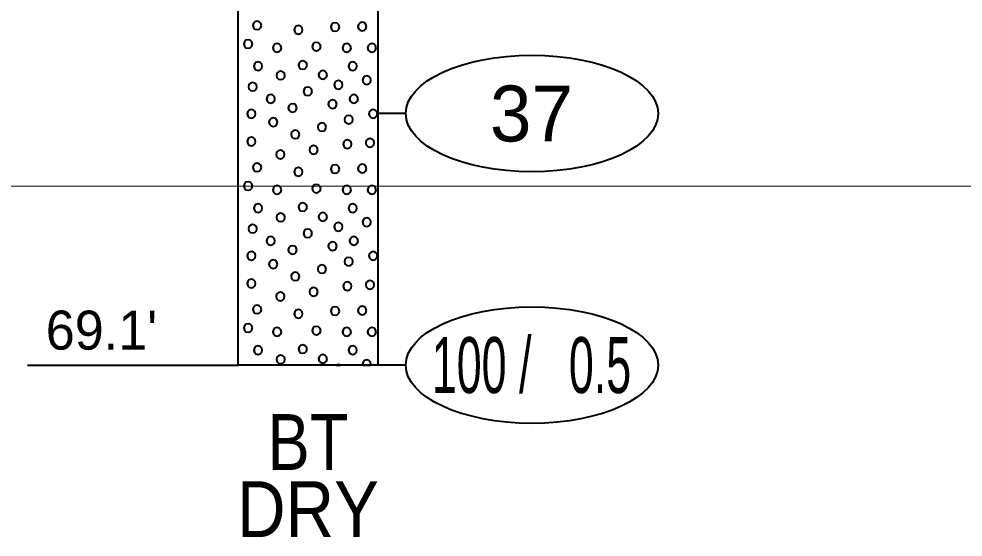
# Model space of a CAD drawing. Extents: x -582 to 653, y -817 to -3.
# Drawn here: x -45.24 to -28.34, y -765.83 to -756.56 of the extents above; entities that cross this region are included whole.
import ezdxf
from ezdxf.enums import TextEntityAlignment as Align

# ---------------------------------------------------------------- set-up
doc = ezdxf.new("R2010")
doc.units = 0
doc.header["$LTSCALE"] = 0.4
doc.layers.add('27', color=7, linetype='Continuous', lineweight=40)
doc.layers.add('7', color=7, linetype='Continuous', lineweight=13)

msp = doc.modelspace()

# ---------------------------------------------------------------- linework, layer by layer
at = {"layer": '27'}
for p, q in [((-38.3189, -758.2526), (-38.8189, -758.2526)), ((-45.0863, -762.7525), (-41.3189, -762.7525)), ((-38.3189, -762.7526), (-38.8189, -762.7526))]:
    msp.add_line(p, q, dxfattribs=at)
for points in [[(-41.3189, -754.6526), (-38.8189, -754.6526), (-38.8189, -762.7525), (-41.3189, -762.7525)], [(-40.9031, -756.6759), (-40.9133, -756.6378), (-40.9412, -756.61), (-40.9793, -756.5997), (-41.0174, -756.61), (-41.0453, -756.6378), (-41.0555, -756.6759), (-41.0453, -756.714), (-41.0174, -756.7419), (-40.9793, -756.7521), (-40.9412, -756.7419), (-40.9133, -756.714)], [(-40.1645, -756.756), (-40.1747, -756.7179), (-40.2026, -756.69), (-40.2407, -756.6798), (-40.2788, -756.69), (-40.3067, -756.7179), (-40.3169, -756.756), (-40.3067, -756.7941), (-40.2788, -756.822), (-40.2407, -756.8322), (-40.2026, -756.822), (-40.1747, -756.7941)], [(-39.5072, -756.7052), (-39.5174, -756.6671), (-39.5453, -756.6392), (-39.5834, -756.629), (-39.6215, -756.6392), (-39.6494, -756.6671), (-39.6596, -756.7052), (-39.6494, -756.7433), (-39.6215, -756.7712), (-39.5834, -756.7814), (-39.5453, -756.7712), (-39.5174, -756.7433)], [(-39.0216, -756.6976), (-39.0318, -756.6595), (-39.0597, -756.6316), (-39.0978, -756.6214), (-39.1359, -756.6316), (-39.1638, -756.6595), (-39.174, -756.6976), (-39.1638, -756.7357), (-39.1359, -756.7636), (-39.0978, -756.7738), (-39.0597, -756.7636), (-39.0318, -756.7357)], [(-41.0645, -757.009), (-41.0747, -756.9709), (-41.1026, -756.943), (-41.1407, -756.9328), (-41.1788, -756.943), (-41.2067, -756.9709), (-41.2169, -757.009), (-41.2067, -757.0471), (-41.1788, -757.075), (-41.1407, -757.0852), (-41.1026, -757.075), (-41.0747, -757.0471)], [(-40.5458, -757.0789), (-40.5561, -757.0408), (-40.5839, -757.0129), (-40.622, -757.0027), (-40.6601, -757.0129), (-40.688, -757.0408), (-40.6982, -757.0789), (-40.688, -757.117), (-40.6601, -757.1449), (-40.622, -757.1551), (-40.5839, -757.1449), (-40.5561, -757.117)], [(-39.8416, -757.0561), (-39.8518, -757.018), (-39.8797, -756.9901), (-39.9178, -756.9799), (-39.9559, -756.9901), (-39.9838, -757.018), (-39.994, -757.0561), (-39.9838, -757.0942), (-39.9559, -757.122), (-39.9178, -757.1323), (-39.8797, -757.122), (-39.8518, -757.0942)], [(-39.2987, -757.0789), (-39.3089, -757.0408), (-39.3368, -757.0129), (-39.3749, -757.0027), (-39.413, -757.0129), (-39.4409, -757.0408), (-39.4511, -757.0789), (-39.4409, -757.117), (-39.413, -757.1449), (-39.3749, -757.1551), (-39.3368, -757.1449), (-39.3089, -757.117)], [(-38.8487, -757.0789), (-38.8589, -757.0408), (-38.8868, -757.0129), (-38.9249, -757.0027), (-38.963, -757.0129), (-38.9909, -757.0408), (-39.0011, -757.0789), (-38.9909, -757.117), (-38.963, -757.1449), (-38.9249, -757.1551), (-38.8868, -757.1449), (-38.8589, -757.117)], [(-40.887, -757.4052), (-40.8972, -757.3671), (-40.9251, -757.3392), (-40.9632, -757.329), (-41.0013, -757.3392), (-41.0292, -757.3671), (-41.0394, -757.4052), (-41.0292, -757.4433), (-41.0013, -757.4712), (-40.9632, -757.4814), (-40.9251, -757.4712), (-40.8972, -757.4433)], [(-40.086, -757.3856), (-40.0962, -757.3475), (-40.1241, -757.3196), (-40.1622, -757.3094), (-40.2003, -757.3196), (-40.2282, -757.3475), (-40.2384, -757.3856), (-40.2282, -757.4237), (-40.2003, -757.4516), (-40.1622, -757.4618), (-40.1241, -757.4516), (-40.0962, -757.4237)], [(-39.1924, -757.4053), (-39.2026, -757.3672), (-39.2305, -757.3393), (-39.2686, -757.3291), (-39.3067, -757.3393), (-39.3346, -757.3672), (-39.3448, -757.4053), (-39.3346, -757.4434), (-39.3067, -757.4713), (-39.2686, -757.4815), (-39.2305, -757.4713), (-39.2026, -757.4434)], [(-40.482, -757.5705), (-40.4923, -757.5324), (-40.5201, -757.5045), (-40.5582, -757.4943), (-40.5963, -757.5045), (-40.6242, -757.5324), (-40.6344, -757.5705), (-40.6242, -757.6086), (-40.5963, -757.6365), (-40.5582, -757.6467), (-40.5201, -757.6365), (-40.4923, -757.6086)], [(-39.727, -757.5615), (-39.7372, -757.5234), (-39.7651, -757.4955), (-39.8032, -757.4853), (-39.8413, -757.4955), (-39.8692, -757.5234), (-39.8794, -757.5615), (-39.8692, -757.5996), (-39.8413, -757.6275), (-39.8032, -757.6377), (-39.7651, -757.6275), (-39.7372, -757.5996)], [(-38.9415, -757.6574), (-38.9517, -757.6193), (-38.9796, -757.5914), (-39.0177, -757.5812), (-39.0558, -757.5914), (-39.0837, -757.6193), (-39.0939, -757.6574), (-39.0837, -757.6955), (-39.0558, -757.7234), (-39.0177, -757.7336), (-38.9796, -757.7234), (-38.9517, -757.6955)], [(-40.9832, -757.7731), (-40.9934, -757.735), (-41.0213, -757.7071), (-41.0594, -757.6969), (-41.0975, -757.7071), (-41.1254, -757.735), (-41.1356, -757.7731), (-41.1254, -757.8112), (-41.0975, -757.839), (-41.0594, -757.8493), (-41.0213, -757.839), (-40.9934, -757.8112)], [(-39.9971, -757.8563), (-40.0073, -757.8182), (-40.0352, -757.7903), (-40.0733, -757.7801), (-40.1114, -757.7903), (-40.1393, -757.8182), (-40.1495, -757.8563), (-40.1393, -757.8944), (-40.1114, -757.9222), (-40.0733, -757.9325), (-40.0352, -757.9222), (-40.0073, -757.8944)], [(-39.4487, -757.7387), (-39.459, -757.7006), (-39.4868, -757.6727), (-39.5249, -757.6625), (-39.563, -757.6727), (-39.5909, -757.7006), (-39.6011, -757.7387), (-39.5909, -757.7768), (-39.563, -757.8047), (-39.5249, -757.8149), (-39.4868, -757.8047), (-39.459, -757.7768)], [(-40.6603, -757.9917), (-40.6705, -757.9536), (-40.6984, -757.9257), (-40.7365, -757.9155), (-40.7746, -757.9257), (-40.8025, -757.9536), (-40.8127, -757.9917), (-40.8025, -758.0298), (-40.7746, -758.0577), (-40.7365, -758.0679), (-40.6984, -758.0577), (-40.6705, -758.0298)], [(-39.1716, -757.9917), (-39.1818, -757.9536), (-39.2097, -757.9257), (-39.2478, -757.9155), (-39.2859, -757.9257), (-39.3138, -757.9536), (-39.324, -757.9917), (-39.3138, -758.0298), (-39.2859, -758.0577), (-39.2478, -758.0679), (-39.2097, -758.0577), (-39.1818, -758.0298)], [(-40.2687, -758.1532), (-40.2789, -758.1151), (-40.3068, -758.0872), (-40.3449, -758.077), (-40.383, -758.0872), (-40.4109, -758.1151), (-40.4211, -758.1532), (-40.4109, -758.1913), (-40.383, -758.2192), (-40.3449, -758.2294), (-40.3068, -758.2192), (-40.2789, -758.1913)], [(-39.553, -758.0845), (-39.5632, -758.0464), (-39.5911, -758.0185), (-39.6292, -758.0083), (-39.6673, -758.0185), (-39.6952, -758.0464), (-39.7054, -758.0845), (-39.6952, -758.1226), (-39.6673, -758.1505), (-39.6292, -758.1607), (-39.5911, -758.1505), (-39.5632, -758.1226)], [(-41.006, -758.2574), (-41.0163, -758.2193), (-41.0441, -758.1914), (-41.0822, -758.1812), (-41.1203, -758.1914), (-41.1482, -758.2193), (-41.1584, -758.2574), (-41.1482, -758.2955), (-41.1203, -758.3234), (-41.0822, -758.3336), (-41.0441, -758.3234), (-41.0163, -758.2955)], [(-39.2644, -758.3617), (-39.2746, -758.3236), (-39.3025, -758.2957), (-39.3406, -758.2855), (-39.3787, -758.2957), (-39.4066, -758.3236), (-39.4168, -758.3617), (-39.4066, -758.3998), (-39.3787, -758.4276), (-39.3406, -758.4379), (-39.3025, -758.4276), (-39.2746, -758.3998)], [(-38.8258, -758.2574), (-38.836, -758.2193), (-38.8639, -758.1914), (-38.902, -758.1812), (-38.9401, -758.1914), (-38.968, -758.2193), (-38.9782, -758.2574), (-38.968, -758.2955), (-38.9401, -758.3234), (-38.902, -758.3336), (-38.8639, -758.3234), (-38.836, -758.2955)], [(-40.6145, -758.4074), (-40.6247, -758.3693), (-40.6526, -758.3414), (-40.6907, -758.3312), (-40.7288, -758.3414), (-40.7567, -758.3693), (-40.7669, -758.4074), (-40.7567, -758.4455), (-40.7288, -758.4734), (-40.6907, -758.4836), (-40.6526, -758.4734), (-40.6247, -758.4455)], [(-39.7424, -758.4951), (-39.7526, -758.457), (-39.7805, -758.4291), (-39.8186, -758.4189), (-39.8567, -758.4291), (-39.8846, -758.457), (-39.8948, -758.4951), (-39.8846, -758.5332), (-39.8567, -758.5611), (-39.8186, -758.5713), (-39.7805, -758.5611), (-39.7526, -758.5332)], [(-40.2204, -758.6261), (-40.2306, -758.588), (-40.2585, -758.5601), (-40.2966, -758.5499), (-40.3347, -758.5601), (-40.3626, -758.588), (-40.3728, -758.6261), (-40.3626, -758.6642), (-40.3347, -758.6921), (-40.2966, -758.7023), (-40.2585, -758.6921), (-40.2306, -758.6642)], [(-41.006, -758.7532), (-41.0163, -758.7151), (-41.0441, -758.6872), (-41.0822, -758.677), (-41.1203, -758.6872), (-41.1482, -758.7151), (-41.1584, -758.7532), (-41.1482, -758.7913), (-41.1203, -758.8192), (-41.0822, -758.8294), (-41.0441, -758.8192), (-41.0163, -758.7913)], [(-39.2873, -758.8002), (-39.2975, -758.7621), (-39.3254, -758.7343), (-39.3635, -758.724), (-39.4016, -758.7343), (-39.4295, -758.7621), (-39.4397, -758.8002), (-39.4295, -758.8383), (-39.4016, -758.8662), (-39.3635, -758.8764), (-39.3254, -758.8662), (-39.2975, -758.8383)], [(-38.883, -758.7761), (-38.8932, -758.738), (-38.9211, -758.7101), (-38.9592, -758.6999), (-38.9973, -758.7101), (-39.0252, -758.738), (-39.0354, -758.7761), (-39.0252, -758.8142), (-38.9973, -758.8421), (-38.9592, -758.8523), (-38.9211, -758.8421), (-38.8932, -758.8142)], [(-40.4874, -758.9846), (-40.4976, -758.9465), (-40.5255, -758.9186), (-40.5636, -758.9084), (-40.6017, -758.9186), (-40.6296, -758.9465), (-40.6398, -758.9846), (-40.6296, -759.0227), (-40.6017, -759.0506), (-40.5636, -759.0608), (-40.5255, -759.0506), (-40.4976, -759.0227)], [(-39.8924, -758.9007), (-39.9026, -758.8626), (-39.9305, -758.8347), (-39.9686, -758.8245), (-40.0067, -758.8347), (-40.0346, -758.8626), (-40.0448, -758.9007), (-40.0346, -758.9388), (-40.0067, -758.9667), (-39.9686, -758.9769), (-39.9305, -758.9667), (-39.9026, -758.9388)], [(-40.9031, -759.2159), (-40.9133, -759.1778), (-40.9412, -759.15), (-40.9793, -759.1397), (-41.0174, -759.15), (-41.0453, -759.1778), (-41.0555, -759.2159), (-41.0453, -759.254), (-41.0174, -759.2819), (-40.9793, -759.2921), (-40.9412, -759.2819), (-40.9133, -759.254)], [(-40.1645, -759.296), (-40.1747, -759.2579), (-40.2026, -759.23), (-40.2407, -759.2198), (-40.2788, -759.23), (-40.3067, -759.2579), (-40.3169, -759.296), (-40.3067, -759.3341), (-40.2788, -759.362), (-40.2407, -759.3722), (-40.2026, -759.362), (-40.1747, -759.3341)], [(-39.5072, -759.2452), (-39.5174, -759.2071), (-39.5453, -759.1792), (-39.5834, -759.169), (-39.6215, -759.1792), (-39.6494, -759.2071), (-39.6596, -759.2452), (-39.6494, -759.2833), (-39.6215, -759.3112), (-39.5834, -759.3214), (-39.5453, -759.3112), (-39.5174, -759.2833)], [(-39.0216, -759.2376), (-39.0318, -759.1995), (-39.0597, -759.1716), (-39.0978, -759.1614), (-39.1359, -759.1716), (-39.1638, -759.1995), (-39.174, -759.2376), (-39.1638, -759.2757), (-39.1359, -759.3036), (-39.0978, -759.3138), (-39.0597, -759.3036), (-39.0318, -759.2757)], [(-41.0645, -759.549), (-41.0747, -759.5109), (-41.1026, -759.483), (-41.1407, -759.4728), (-41.1788, -759.483), (-41.2067, -759.5109), (-41.2169, -759.549), (-41.2067, -759.5871), (-41.1788, -759.615), (-41.1407, -759.6252), (-41.1026, -759.615), (-41.0747, -759.5871)], [(-40.5458, -759.6189), (-40.5561, -759.5808), (-40.5839, -759.5529), (-40.622, -759.5427), (-40.6601, -759.5529), (-40.688, -759.5808), (-40.6982, -759.6189), (-40.688, -759.657), (-40.6601, -759.6849), (-40.622, -759.6951), (-40.5839, -759.6849), (-40.5561, -759.657)], [(-39.8416, -759.5961), (-39.8518, -759.558), (-39.8797, -759.5301), (-39.9178, -759.5199), (-39.9559, -759.5301), (-39.9838, -759.558), (-39.994, -759.5961), (-39.9838, -759.6342), (-39.9559, -759.662), (-39.9178, -759.6723), (-39.8797, -759.662), (-39.8518, -759.6342)], [(-39.2987, -759.6189), (-39.3089, -759.5808), (-39.3368, -759.5529), (-39.3749, -759.5427), (-39.413, -759.5529), (-39.4409, -759.5808), (-39.4511, -759.6189), (-39.4409, -759.657), (-39.413, -759.6849), (-39.3749, -759.6951), (-39.3368, -759.6849), (-39.3089, -759.657)], [(-38.8487, -759.6189), (-38.8589, -759.5808), (-38.8868, -759.5529), (-38.9249, -759.5427), (-38.963, -759.5529), (-38.9909, -759.5808), (-39.0011, -759.6189), (-38.9909, -759.657), (-38.963, -759.6849), (-38.9249, -759.6951), (-38.8868, -759.6849), (-38.8589, -759.657)], [(-40.887, -759.9452), (-40.8972, -759.9071), (-40.9251, -759.8792), (-40.9632, -759.869), (-41.0013, -759.8792), (-41.0292, -759.9071), (-41.0394, -759.9452), (-41.0292, -759.9833), (-41.0013, -760.0112), (-40.9632, -760.0214), (-40.9251, -760.0112), (-40.8972, -759.9833)], [(-40.086, -759.9256), (-40.0962, -759.8875), (-40.1241, -759.8596), (-40.1622, -759.8494), (-40.2003, -759.8596), (-40.2282, -759.8875), (-40.2384, -759.9256), (-40.2282, -759.9637), (-40.2003, -759.9916), (-40.1622, -760.0018), (-40.1241, -759.9916), (-40.0962, -759.9637)], [(-39.1924, -759.9453), (-39.2026, -759.9072), (-39.2305, -759.8793), (-39.2686, -759.8691), (-39.3067, -759.8793), (-39.3346, -759.9072), (-39.3448, -759.9453), (-39.3346, -759.9834), (-39.3067, -760.0113), (-39.2686, -760.0215), (-39.2305, -760.0113), (-39.2026, -759.9834)], [(-40.482, -760.1105), (-40.4923, -760.0724), (-40.5201, -760.0445), (-40.5582, -760.0343), (-40.5963, -760.0445), (-40.6242, -760.0724), (-40.6344, -760.1105), (-40.6242, -760.1486), (-40.5963, -760.1765), (-40.5582, -760.1867), (-40.5201, -760.1765), (-40.4923, -760.1486)], [(-39.727, -760.1015), (-39.7372, -760.0634), (-39.7651, -760.0355), (-39.8032, -760.0253), (-39.8413, -760.0355), (-39.8692, -760.0634), (-39.8794, -760.1015), (-39.8692, -760.1396), (-39.8413, -760.1675), (-39.8032, -760.1777), (-39.7651, -760.1675), (-39.7372, -760.1396)], [(-38.9415, -760.1974), (-38.9517, -760.1593), (-38.9796, -760.1314), (-39.0177, -760.1212), (-39.0558, -760.1314), (-39.0837, -760.1593), (-39.0939, -760.1974), (-39.0837, -760.2355), (-39.0558, -760.2634), (-39.0177, -760.2736), (-38.9796, -760.2634), (-38.9517, -760.2355)], [(-40.9832, -760.3131), (-40.9934, -760.275), (-41.0213, -760.2471), (-41.0594, -760.2369), (-41.0975, -760.2471), (-41.1254, -760.275), (-41.1356, -760.3131), (-41.1254, -760.3512), (-41.0975, -760.379), (-41.0594, -760.3893), (-41.0213, -760.379), (-40.9934, -760.3512)], [(-39.9971, -760.3963), (-40.0073, -760.3582), (-40.0352, -760.3303), (-40.0733, -760.3201), (-40.1114, -760.3303), (-40.1393, -760.3582), (-40.1495, -760.3963), (-40.1393, -760.4344), (-40.1114, -760.4622), (-40.0733, -760.4725), (-40.0352, -760.4622), (-40.0073, -760.4344)], [(-39.4487, -760.2787), (-39.459, -760.2406), (-39.4868, -760.2127), (-39.5249, -760.2025), (-39.563, -760.2127), (-39.5909, -760.2406), (-39.6011, -760.2787), (-39.5909, -760.3168), (-39.563, -760.3447), (-39.5249, -760.3549), (-39.4868, -760.3447), (-39.459, -760.3168)], [(-40.6603, -760.5317), (-40.6705, -760.4936), (-40.6984, -760.4657), (-40.7365, -760.4555), (-40.7746, -760.4657), (-40.8025, -760.4936), (-40.8127, -760.5317), (-40.8025, -760.5698), (-40.7746, -760.5977), (-40.7365, -760.6079), (-40.6984, -760.5977), (-40.6705, -760.5698)], [(-39.1716, -760.5317), (-39.1818, -760.4936), (-39.2097, -760.4657), (-39.2478, -760.4555), (-39.2859, -760.4657), (-39.3138, -760.4936), (-39.324, -760.5317), (-39.3138, -760.5698), (-39.2859, -760.5977), (-39.2478, -760.6079), (-39.2097, -760.5977), (-39.1818, -760.5698)], [(-40.2687, -760.6932), (-40.2789, -760.6551), (-40.3068, -760.6272), (-40.3449, -760.617), (-40.383, -760.6272), (-40.4109, -760.6551), (-40.4211, -760.6932), (-40.4109, -760.7313), (-40.383, -760.7592), (-40.3449, -760.7694), (-40.3068, -760.7592), (-40.2789, -760.7313)], [(-39.553, -760.6245), (-39.5632, -760.5864), (-39.5911, -760.5585), (-39.6292, -760.5483), (-39.6673, -760.5585), (-39.6952, -760.5864), (-39.7054, -760.6245), (-39.6952, -760.6626), (-39.6673, -760.6905), (-39.6292, -760.7007), (-39.5911, -760.6905), (-39.5632, -760.6626)], [(-41.006, -760.7974), (-41.0163, -760.7593), (-41.0441, -760.7314), (-41.0822, -760.7212), (-41.1203, -760.7314), (-41.1482, -760.7593), (-41.1584, -760.7974), (-41.1482, -760.8355), (-41.1203, -760.8634), (-41.0822, -760.8736), (-41.0441, -760.8634), (-41.0163, -760.8355)], [(-39.2644, -760.9017), (-39.2746, -760.8636), (-39.3025, -760.8357), (-39.3406, -760.8255), (-39.3787, -760.8357), (-39.4066, -760.8636), (-39.4168, -760.9017), (-39.4066, -760.9398), (-39.3787, -760.9676), (-39.3406, -760.9779), (-39.3025, -760.9676), (-39.2746, -760.9398)], [(-38.8258, -760.7974), (-38.836, -760.7593), (-38.8639, -760.7314), (-38.902, -760.7212), (-38.9401, -760.7314), (-38.968, -760.7593), (-38.9782, -760.7974), (-38.968, -760.8355), (-38.9401, -760.8634), (-38.902, -760.8736), (-38.8639, -760.8634), (-38.836, -760.8355)], [(-40.6145, -760.9474), (-40.6247, -760.9093), (-40.6526, -760.8814), (-40.6907, -760.8712), (-40.7288, -760.8814), (-40.7567, -760.9093), (-40.7669, -760.9474), (-40.7567, -760.9855), (-40.7288, -761.0134), (-40.6907, -761.0236), (-40.6526, -761.0134), (-40.6247, -760.9855)], [(-39.7424, -761.0351), (-39.7526, -760.997), (-39.7805, -760.9691), (-39.8186, -760.9589), (-39.8567, -760.9691), (-39.8846, -760.997), (-39.8948, -761.0351), (-39.8846, -761.0732), (-39.8567, -761.1011), (-39.8186, -761.1113), (-39.7805, -761.1011), (-39.7526, -761.0732)], [(-40.2204, -761.1661), (-40.2306, -761.128), (-40.2585, -761.1001), (-40.2966, -761.0899), (-40.3347, -761.1001), (-40.3626, -761.128), (-40.3728, -761.1661), (-40.3626, -761.2042), (-40.3347, -761.2321), (-40.2966, -761.2423), (-40.2585, -761.2321), (-40.2306, -761.2042)], [(-41.006, -761.2932), (-41.0163, -761.2551), (-41.0441, -761.2272), (-41.0822, -761.217), (-41.1203, -761.2272), (-41.1482, -761.2551), (-41.1584, -761.2932), (-41.1482, -761.3313), (-41.1203, -761.3592), (-41.0822, -761.3694), (-41.0441, -761.3592), (-41.0163, -761.3313)], [(-39.2873, -761.3402), (-39.2975, -761.3021), (-39.3254, -761.2743), (-39.3635, -761.264), (-39.4016, -761.2743), (-39.4295, -761.3021), (-39.4397, -761.3402), (-39.4295, -761.3783), (-39.4016, -761.4062), (-39.3635, -761.4164), (-39.3254, -761.4062), (-39.2975, -761.3783)], [(-38.883, -761.3161), (-38.8932, -761.278), (-38.9211, -761.2501), (-38.9592, -761.2399), (-38.9973, -761.2501), (-39.0252, -761.278), (-39.0354, -761.3161), (-39.0252, -761.3542), (-38.9973, -761.3821), (-38.9592, -761.3923), (-38.9211, -761.3821), (-38.8932, -761.3542)], [(-40.4874, -761.5246), (-40.4976, -761.4865), (-40.5255, -761.4586), (-40.5636, -761.4484), (-40.6017, -761.4586), (-40.6296, -761.4865), (-40.6398, -761.5246), (-40.6296, -761.5627), (-40.6017, -761.5906), (-40.5636, -761.6008), (-40.5255, -761.5906), (-40.4976, -761.5627)], [(-39.8924, -761.4407), (-39.9026, -761.4026), (-39.9305, -761.3747), (-39.9686, -761.3645), (-40.0067, -761.3747), (-40.0346, -761.4026), (-40.0448, -761.4407), (-40.0346, -761.4788), (-40.0067, -761.5067), (-39.9686, -761.5169), (-39.9305, -761.5067), (-39.9026, -761.4788)], [(-40.9031, -761.7559), (-40.9133, -761.7178), (-40.9412, -761.69), (-40.9793, -761.6797), (-41.0174, -761.69), (-41.0453, -761.7178), (-41.0555, -761.7559), (-41.0453, -761.794), (-41.0174, -761.8219), (-40.9793, -761.8321), (-40.9412, -761.8219), (-40.9133, -761.794)], [(-40.1645, -761.836), (-40.1747, -761.7979), (-40.2026, -761.77), (-40.2407, -761.7598), (-40.2788, -761.77), (-40.3067, -761.7979), (-40.3169, -761.836), (-40.3067, -761.8741), (-40.2788, -761.902), (-40.2407, -761.9122), (-40.2026, -761.902), (-40.1747, -761.8741)], [(-39.5072, -761.7852), (-39.5174, -761.7471), (-39.5453, -761.7192), (-39.5834, -761.709), (-39.6215, -761.7192), (-39.6494, -761.7471), (-39.6596, -761.7852), (-39.6494, -761.8233), (-39.6215, -761.8512), (-39.5834, -761.8614), (-39.5453, -761.8512), (-39.5174, -761.8233)], [(-39.0216, -761.7776), (-39.0318, -761.7395), (-39.0597, -761.7116), (-39.0978, -761.7014), (-39.1359, -761.7116), (-39.1638, -761.7395), (-39.174, -761.7776), (-39.1638, -761.8157), (-39.1359, -761.8436), (-39.0978, -761.8538), (-39.0597, -761.8436), (-39.0318, -761.8157)], [(-41.0645, -762.089), (-41.0747, -762.0509), (-41.1026, -762.023), (-41.1407, -762.0128), (-41.1788, -762.023), (-41.2067, -762.0509), (-41.2169, -762.089), (-41.2067, -762.1271), (-41.1788, -762.155), (-41.1407, -762.1652), (-41.1026, -762.155), (-41.0747, -762.1271)], [(-40.5458, -762.1589), (-40.5561, -762.1208), (-40.5839, -762.0929), (-40.622, -762.0827), (-40.6601, -762.0929), (-40.688, -762.1208), (-40.6982, -762.1589), (-40.688, -762.197), (-40.6601, -762.2249), (-40.622, -762.2351), (-40.5839, -762.2249), (-40.5561, -762.197)], [(-39.8416, -762.1361), (-39.8518, -762.098), (-39.8797, -762.0701), (-39.9178, -762.0599), (-39.9559, -762.0701), (-39.9838, -762.098), (-39.994, -762.1361), (-39.9838, -762.1742), (-39.9559, -762.202), (-39.9178, -762.2123), (-39.8797, -762.202), (-39.8518, -762.1742)], [(-39.2987, -762.1589), (-39.3089, -762.1208), (-39.3368, -762.0929), (-39.3749, -762.0827), (-39.413, -762.0929), (-39.4409, -762.1208), (-39.4511, -762.1589), (-39.4409, -762.197), (-39.413, -762.2249), (-39.3749, -762.2351), (-39.3368, -762.2249), (-39.3089, -762.197)], [(-38.8487, -762.1589), (-38.8589, -762.1208), (-38.8868, -762.0929), (-38.9249, -762.0827), (-38.963, -762.0929), (-38.9909, -762.1208), (-39.0011, -762.1589), (-38.9909, -762.197), (-38.963, -762.2249), (-38.9249, -762.2351), (-38.8868, -762.2249), (-38.8589, -762.197)], [(-40.887, -762.4852), (-40.8972, -762.4471), (-40.9251, -762.4192), (-40.9632, -762.409), (-41.0013, -762.4192), (-41.0292, -762.4471), (-41.0394, -762.4852), (-41.0292, -762.5233), (-41.0013, -762.5512), (-40.9632, -762.5614), (-40.9251, -762.5512), (-40.8972, -762.5233)], [(-40.086, -762.4656), (-40.0962, -762.4275), (-40.1241, -762.3996), (-40.1622, -762.3894), (-40.2003, -762.3996), (-40.2282, -762.4275), (-40.2384, -762.4656), (-40.2282, -762.5037), (-40.2003, -762.5316), (-40.1622, -762.5418), (-40.1241, -762.5316), (-40.0962, -762.5037)], [(-39.1924, -762.4853), (-39.2026, -762.4472), (-39.2305, -762.4193), (-39.2686, -762.4091), (-39.3067, -762.4193), (-39.3346, -762.4472), (-39.3448, -762.4853), (-39.3346, -762.5234), (-39.3067, -762.5513), (-39.2686, -762.5615), (-39.2305, -762.5513), (-39.2026, -762.5234)], [(-40.482, -762.6505), (-40.4923, -762.6124), (-40.5201, -762.5845), (-40.5582, -762.5743), (-40.5963, -762.5845), (-40.6242, -762.6124), (-40.6344, -762.6505), (-40.6242, -762.6886), (-40.5963, -762.7165), (-40.5582, -762.7267), (-40.5201, -762.7165), (-40.4923, -762.6886)], [(-39.727, -762.6415), (-39.7372, -762.6034), (-39.7651, -762.5755), (-39.8032, -762.5653), (-39.8413, -762.5755), (-39.8692, -762.6034), (-39.8794, -762.6415), (-39.8692, -762.6796), (-39.8413, -762.7075), (-39.8032, -762.7177), (-39.7651, -762.7075), (-39.7372, -762.6796)], [(-38.9415, -762.7374), (-38.9517, -762.6993), (-38.9796, -762.6714), (-39.0177, -762.6612), (-39.0558, -762.6714), (-39.0837, -762.6993), (-39.0939, -762.7374), (-39.0898, -762.7526), (-38.9456, -762.7526)], [(-39.5249, -762.7425), (-39.5624, -762.7526), (-39.4875, -762.7526)]]:
    msp.add_lwpolyline(points, close=True, dxfattribs=at)
for centre in [(-36.0615, -758.2525), (-36.0615, -762.7526)]:
    msp.add_ellipse(centre, major_axis=(2.2574, 0), ratio=0.461538, dxfattribs=at)
at = {"layer": '7'}
for p, q in [((-81.3332, -759.5526), (-41.3189, -759.5526)), ((-61.5437, -759.5526), (-28.9686, -759.5526)), ((-38.8189, -759.5526), (9.9605, -759.5526))]:
    msp.add_line(p, q, dxfattribs=at)

# ---------------------------------------------------------------- texts
at = {"layer": '27'}
msp.add_text('37', height=1, dxfattribs=at).set_placement((-36.069, -758.7526), align=Align.CENTER)
msp.add_text("69.1'", height=0.6976, dxfattribs=at).set_placement((-44.7623, -762.4762))
for s, width, p in [('100 /   0.5', 0.6, (-36.0689, -763.2526)), ('BT', 0.85, (-40.0689, -764.6295)), ('DRY', 0.9, (-40.0689, -765.8295))]:
    msp.add_text(s, height=1, dxfattribs=dict(at, width=width)).set_placement(p, align=Align.CENTER)

doc.saveas('drawing.dxf')
